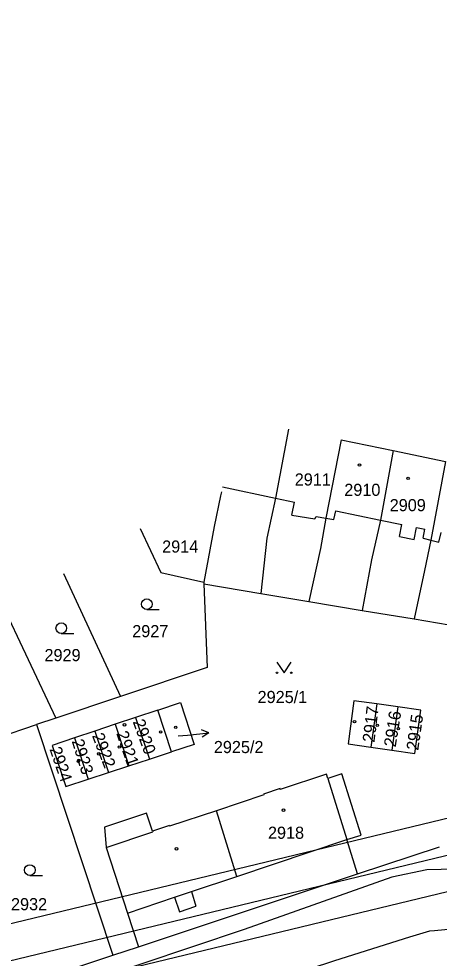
# Model space of a CAD drawing. Extents: x -738085 to -734306, y -1122197 to -1119753.
# Drawn here: x -735058.2 to -734999.3, y -1120116 to -1119984.4 of the extents above; entities that cross this region are included whole.
import ezdxf

# ---------------------------------------------------------------- set-up
doc = ezdxf.new("R2010")
doc.units = 0
for name, color, linetype in [('Hranice parcel', 7, 'Continuous'), ('Parcelní čísla', 7, 'Continuous'), ('Pop  PČ popisy', 7, 'Continuous'), ('Vnitřní kresba', 7, 'Continuous'), ('Vrstva 1', 7, 'Continuous'), ('Značky budov', 7, 'Continuous'), ('Značky kultur', 7, 'Continuous')]:
    doc.layers.add(name, color=color, linetype=linetype)

msp = doc.modelspace()

# ---------------------------------------------------------------- linework, layer by layer
at = {"layer": 'Hranice parcel'}
for p, q in [((-735013.09, -1120043.39), (-735005.77, -1120044.9)), ((-735005.77, -1120044.9), (-734998.47, -1120046.4)), ((-735051.98, -1120062.1), (-735043.98, -1120079.35)), ((-735032.29, -1120063.35), (-735032.33, -1120063.58)), ((-735032.33, -1120063.58), (-735024.34, -1120064.91)), ((-735024.34, -1120064.91), (-735017.62, -1120066.03)), ((-735060.78, -1120065.94), (-735053.06, -1120082.39)), ((-735017.62, -1120066.03), (-735010.12, -1120067.28)), ((-735010.12, -1120067.28), (-735002.84, -1120068.49)), ((-735002.84, -1120068.49), (-734995.38, -1120069.73)), ((-735043.98, -1120079.35), (-735053.06, -1120082.39)), ((-735008.09, -1120080.39), (-735008.92, -1120086.44)), ((-735005.14, -1120080.82), (-735008.09, -1120080.39)), ((-735038.77, -1120081.26), (-735041.87, -1120082.3)), ((-735036.84, -1120087.1), (-735038.77, -1120081.26)), ((-735005.14, -1120080.82), (-735005.96, -1120086.86)), ((-735053.06, -1120082.39), (-735055.76, -1120083.29)), ((-735041.87, -1120082.3), (-735044.74, -1120083.25)), ((-735041.87, -1120082.3), (-735039.94, -1120088.12)), ((-735068.46, -1120087.54), (-735055.76, -1120083.29)), ((-735055.76, -1120083.29), (-735045.05, -1120115.6)), ((-735047.58, -1120084.21), (-735050.44, -1120085.16)), ((-735044.74, -1120083.25), (-735047.58, -1120084.21)), ((-735047.58, -1120084.21), (-735045.65, -1120090.01)), ((-735044.74, -1120083.25), (-735042.8, -1120089.07)), ((-735050.44, -1120085.16), (-735048.5, -1120090.95)), ((-735008.92, -1120086.44), (-735005.96, -1120086.86)), ((-735042.8, -1120089.07), (-735039.94, -1120088.12)), ((-735039.94, -1120088.12), (-735036.84, -1120087.1)), ((-735045.65, -1120090.01), (-735042.8, -1120089.07)), ((-735048.5, -1120090.95), (-735045.65, -1120090.01)), ((-735010.79, -1120104.22), (-734999.31, -1120100.41)), ((-735045.05, -1120115.6), (-735041.45, -1120114.41)), ((-735061.75, -1120121.13), (-735045.05, -1120115.6))]:
    msp.add_line(p, q, dxfattribs=at)
for points in [[(-735020.44, -1120041.9), (-735022.27, -1120051.55), (-735023.5, -1120057.17), (-735024.34, -1120064.91)], [(-735013.09, -1120043.39), (-735015.24, -1120054.37), (-735015.99, -1120058.62), (-735017.62, -1120066.03)], [(-735005.77, -1120044.9), (-735007.58, -1120054.63), (-735008.81, -1120060.21), (-735010.12, -1120067.28)], [(-734998.47, -1120046.4), (-735000.5, -1120057.45), (-735001.4, -1120061.7), (-735002.84, -1120068.49)], [(-735029.85, -1120050.67), (-735029.96, -1120051.23), (-735030.88, -1120055.51), (-735032.29, -1120063.35)], [(-735041.25, -1120055.82), (-735038.33, -1120061.98), (-735032.29, -1120063.35)], [(-735032.33, -1120063.58), (-735031.83, -1120075.28), (-735043.98, -1120079.35)], [(-735038.77, -1120081.26), (-735035.57, -1120080.19), (-735033.67, -1120086.06), (-735036.84, -1120087.1)], [(-735008.09, -1120080.39), (-735011.28, -1120079.94), (-735012.09, -1120085.99), (-735008.92, -1120086.44)], [(-735005.96, -1120086.86), (-735002.77, -1120087.32), (-735001.94, -1120081.27), (-735005.14, -1120080.82)], [(-735050.44, -1120085.16), (-735053.55, -1120086.2), (-735051.63, -1120091.98), (-735048.5, -1120090.95)], [(-735010.79, -1120104.22), (-735012.29, -1120099.41), (-735010.29, -1120098.79), (-735012.97, -1120090.2), (-735014.96, -1120090.82), (-735015.15, -1120090.22), (-735021.6, -1120092.37), (-735021.64, -1120092.26), (-735023.97, -1120093.03), (-735023.93, -1120093.15), (-735030.53, -1120095.35), (-735037.1, -1120097.54), (-735037.14, -1120097.42), (-735039.5, -1120098.21), (-735040.33, -1120095.72), (-735046.21, -1120097.68), (-735046.01, -1120100.51), (-735043, -1120109.69), (-735041.45, -1120114.41)], [(-734732.31, -1120124.29), (-734735.07, -1120127.22), (-734738.9, -1120128.4), (-734741.96, -1120128.37), (-734978.31, -1120104.89), (-734995.05, -1120103.5), (-735001.08, -1120103.64), (-735005.96, -1120104.65), (-735026.65, -1120111.99), (-735048.37, -1120119.26), (-735164.14, -1120157.32), (-735176.88, -1120160.91), (-735184.81, -1120162.43), (-735185.96, -1120162.53), (-735190.85, -1120162.98), (-735196.87, -1120162.75), (-735201.79, -1120161.48), (-735203.71, -1120160.98), (-735206.41, -1120159.5), (-735208.64, -1120157.56), (-735225.14, -1120141.26)], [(-735041.45, -1120114.41), (-735026.19, -1120109.34), (-735010.79, -1120104.22)], [(-735187.2, -1120177.07), (-735186.92, -1120175.94), (-735186.47, -1120174.12), (-735185.21, -1120172.48), (-735182.42, -1120171.13), (-735165.98, -1120166.38), (-735013.95, -1120116.34), (-735003.48, -1120113.01), (-735000.64, -1120112.19), (-735000, -1120112.13), (-734996.62, -1120111.83), (-734988.63, -1120112.11), (-734951.68, -1120115.51), (-734795.1, -1120131), (-734756.12, -1120134.99), (-734754.2, -1120137.32), (-734753.31, -1120137.78), (-734734.93, -1120139.52), (-734728.17, -1120141.08), (-734724.68, -1120142.84), (-734723.73, -1120143.69)]]:
    msp.add_lwpolyline(points, dxfattribs=at)
at = {"layer": 'Pop  PČ popisy'}
for p, q in [((-735031.6, -1120084.44), (-735032.65, -1120084.04)), ((-735035.89, -1120084.88), (-735034.59, -1120084.75)), ((-735034.59, -1120084.75), (-735031.6, -1120084.44)), ((-735031.6, -1120084.44), (-735032.55, -1120085.04))]:
    msp.add_line(p, q, dxfattribs=at)
at = {"layer": 'Vnitřní kresba'}
for p, q in [((-735029.72, -1120049.95), (-735022.27, -1120051.55)), ((-735022.27, -1120051.55), (-735019.59, -1120052.12)), ((-735019.98, -1120053.93), (-735019.59, -1120052.12)), ((-735019.98, -1120053.93), (-735016.75, -1120054.45)), ((-735014.1, -1120054.57), (-735013.84, -1120053.35)), ((-735013.84, -1120053.35), (-735007.58, -1120054.63)), ((-735016.75, -1120054.45), (-735016.6, -1120054.12)), ((-735016.6, -1120054.12), (-735015.24, -1120054.37)), ((-735015.24, -1120054.37), (-735014.1, -1120054.57)), ((-735007.58, -1120054.63), (-735004.56, -1120055.24)), ((-735004.9, -1120056.94), (-735004.56, -1120055.24)), ((-735002.86, -1120057.33), (-735002.51, -1120055.66)), ((-735002.51, -1120055.66), (-735001.35, -1120055.9)), ((-735001.61, -1120057.17), (-735001.35, -1120055.9)), ((-734999.38, -1120057.73), (-734999.09, -1120056.36)), ((-735004.9, -1120056.94), (-735002.86, -1120057.33)), ((-735001.61, -1120057.17), (-735000.5, -1120057.45)), ((-735000.5, -1120057.45), (-734999.38, -1120057.73)), ((-735014.96, -1120090.82), (-735012.29, -1120099.41)), ((-735027.67, -1120104.56), (-735030.53, -1120095.35)), ((-735046.01, -1120100.51), (-735039.46, -1120098.33)), ((-735039.5, -1120098.21), (-735039.46, -1120098.33)), ((-735027.67, -1120104.56), (-735012.29, -1120099.41)), ((-735034.05, -1120106.69), (-735027.67, -1120104.56)), ((-735036.42, -1120107.49), (-735034.05, -1120106.69)), ((-735034.05, -1120106.69), (-735033.43, -1120108.73)), ((-735043, -1120109.69), (-735036.42, -1120107.49)), ((-735036.42, -1120107.49), (-735035.74, -1120109.52)), ((-735035.74, -1120109.52), (-735033.43, -1120108.73))]:
    msp.add_line(p, q, dxfattribs=at)
at = {"layer": 'Vrstva 1'}
for points in [[(-734534.27, -1119984.39), (-735554.91, -1120230.88), (-735485.2, -1120519.57), (-734464.55, -1120273.08)], [(-734470.58, -1120269.4), (-735481.51, -1120513.53), (-735548.88, -1120234.56), (-734537.95, -1119990.43)], [(-734541.63, -1119996.45), (-735348.44, -1120191.3), (-735283.42, -1120460.56), (-734476.61, -1120265.71)]]:
    msp.add_lwpolyline(points, close=True, dxfattribs=at)
at = {"layer": 'Značky budov'}
for centre in [(-735010.51, -1120046.92), (-735003.7, -1120048.77), (-735011.21, -1120082.88), (-735043.43, -1120083.32), (-735038.36, -1120084.32), (-735036.25, -1120083.67), (-735008.02, -1120083.4), (-735005.07, -1120083.85), (-735044.15, -1120086.43), (-735049.88, -1120088.43), (-735047.04, -1120087.39), (-735021.16, -1120095.27), (-735036.14, -1120100.69)]:
    msp.add_circle(centre, 0.175, dxfattribs=at)
at = {"layer": 'Značky kultur'}
for p, q in [((-735040.3, -1120067.16), (-735038.55, -1120067.16)), ((-735052.28, -1120070.52), (-735050.53, -1120070.52)), ((-735056.68, -1120104.42), (-735054.93, -1120104.42))]:
    msp.add_line(p, q, dxfattribs=at)
msp.add_lwpolyline([(-735022.07, -1120074.52), (-735021.07, -1120076.02), (-735020.07, -1120074.52)], dxfattribs=at)
for centre, radius in [((-735040.3, -1120066.41), 0.75), ((-735052.28, -1120069.77), 0.75), ((-735022.07, -1120076.02), 0.1), ((-735020.07, -1120076.02), 0.1), ((-735056.68, -1120103.67), 0.75)]:
    msp.add_circle(centre, radius, dxfattribs=at)

# ---------------------------------------------------------------- texts
at = {"layer": 'Parcelní čísla'}
for s, p in [('2911', (-735019.58, -1120049.79)), ('2910', (-735012.64, -1120051.24)), ('2909', (-735006.28, -1120053.39)), ('2914', (-735038.15, -1120059.19)), ('2927', (-735042.34, -1120071.04)), ('2929', (-735054.63, -1120074.4)), ('2925/1', (-735024.78, -1120080.27)), ('2925/2', (-735030.91, -1120087.28)), ('2918', (-735023.33, -1120099.29)), ('2932', (-735059.32, -1120109.3))]:
    msp.add_text(s, height=1.7, dxfattribs=at).set_placement(p)
for s, rotation, p in [('2917', 83, (-735008.42, -1120085.85)), ('2916', 81, (-735005.44, -1120086.51)), ('2920', 290, (-735042.29, -1120082.88)), ('2915', 82, (-735002.28, -1120086.98)), ('2921', 289, (-735044.6, -1120084.51)), ('2923', 287, (-735050.83, -1120085.6)), ('2922', 291, (-735048, -1120084.83)), ('2924', 289, (-735053.95, -1120086.72))]:
    msp.add_text(s, height=1.7, rotation=rotation, dxfattribs=at).set_placement(p)

doc.saveas('drawing.dxf')
